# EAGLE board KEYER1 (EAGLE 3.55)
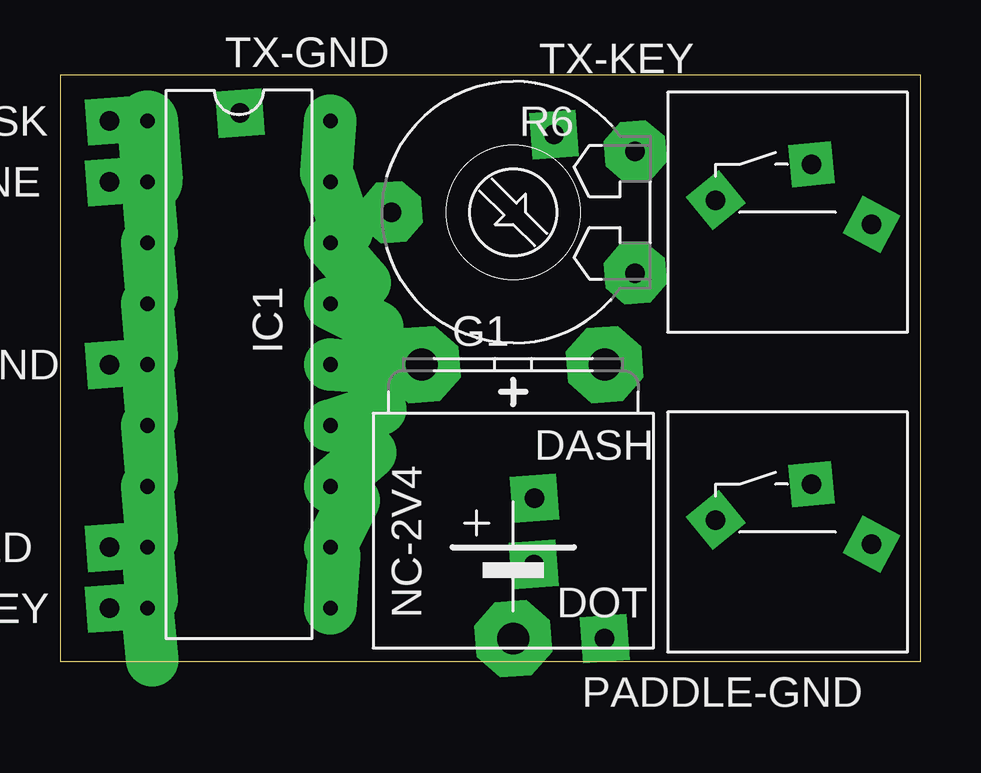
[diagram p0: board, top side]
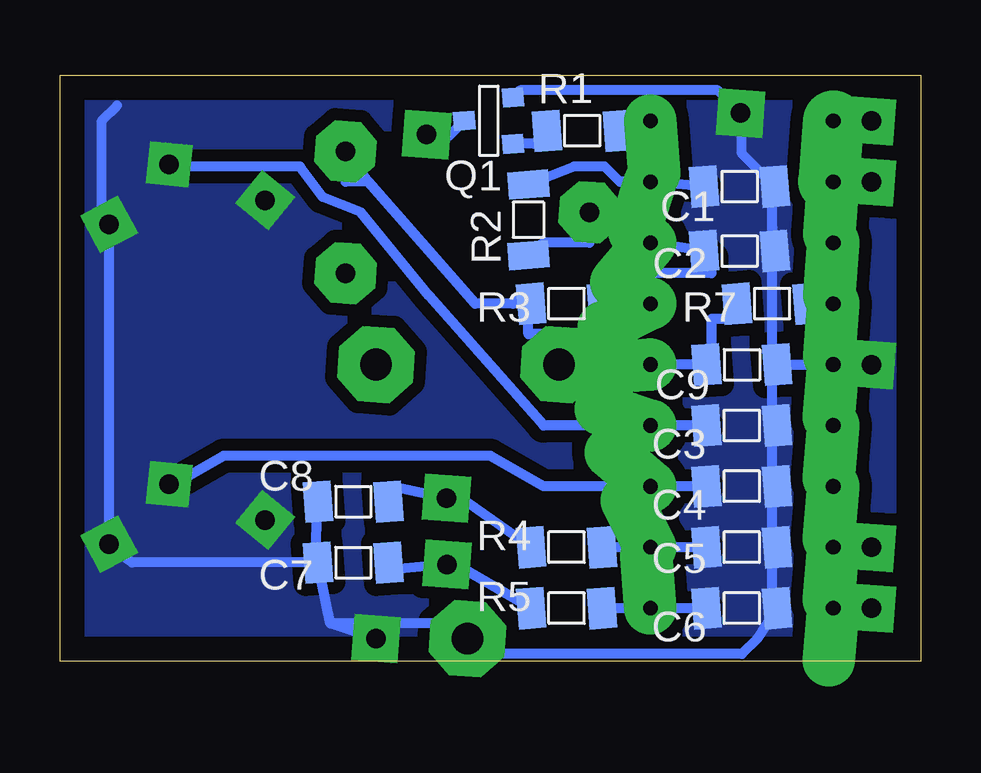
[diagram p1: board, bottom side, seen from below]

Size 35.87 x 24.44 mm. Coordinates in mm from the lower left corner, seen from the top.
Outline: 0,0 35.87,0 35.87,24.44 0,24.44 0,0
Copper layers used: Bottom

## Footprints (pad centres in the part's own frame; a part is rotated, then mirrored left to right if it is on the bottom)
06 = smd 1.143 x 1.702 rotated 4.4:  1.473,0 | smd 1.143 x 1.702 rotated 4.3:  -1.473,0
30R = drill 1.321 pad 3.15 octagon:  -7.62,-3.81;  -7.62,3.81;  3.81,0
L18 = drill 0.61 pad 2.54 offset:  -10.16,-3.81 | drill 0.61 pad 2.184 offset:  -7.62,-3.81;  5.08,-3.81;  7.62,-3.81;  -5.08,-3.81;  -2.54,-3.81;  2.54,-3.81;  0,-3.81;  10.16,-3.81;  10.16,3.81;  7.62,3.81;  5.08,3.81;  2.54,3.81;  0,3.81;  -2.54,3.81;  -5.08,3.81;  -7.62,3.81;  -10.16,3.81
T-23 = smd 0.787 x 0.889 rotated 4.4:  0.991,1.016 | smd 0.787 x 0.889 rotated 4.3:  -0.94,1.016 | smd 0.787 x 0.889 rotated 4.5:  0.025,-1.016
T_LI10 = drill 0.813 pad 2.54 octagon:  -2.54,-5.08;  0,5.08;  2.54,-5.08
Y_SQ10 = drill 0.813 pad 1.778 square:  -0.5,-3.5;  2,-1;  0.5,3
D-SQ2 = drill 0.813 pad 1.93 square:  0,0

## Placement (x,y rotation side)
C1  220n  [06]  7.55,19.8 0 bottom
C2  330pF  [06]  7.55,17.11 0 bottom
C3  1n  [06]  7.46,9.84 180 bottom
C4  1n  [06]  7.46,7.3 180 bottom
C5  1n  [06]  7.46,4.76 180 bottom
C6  1n  [06]  7.46,2.22 180 bottom
C7  1n  [06]  23.65,4.12 0 bottom
C8  1n  [06]  23.65,6.66 0 bottom
C9  100n  [06]  7.46,12.38 0 bottom
G1  NiCd2.4V  [30R]  18.88,4.76 270 top
IC1  16F84P  [L18]  7.46,12.38 270 top
Q1  BC817  [T-23]  18,22.57 270 bottom
R1  22k  [06]  14.1,22.12 180 bottom
R2  1k  [06]  16.34,18.41 270 bottom
R3  100k  [06]  14.76,14.92 180 bottom
R4  1k  [06]  14.76,4.76 180 bottom
R5  1k  [06]  14.76,2.22 180 bottom
R6  100k  [T_LI10]  18.88,18.73 90 top
R7  10k  [06]  6.18,14.92 180 bottom
S1  MSG1  [Y_SQ10]  30.31,5.39 90 top
S2  MSG2  [Y_SQ10]  30.31,18.73 90 top
X1  TX-KEY  [D-SQ2]  20.59,21.97 0 top
X2  DOT  [D-SQ2]  19.74,4.04 0 top
X3  DASH  [D-SQ2]  19.77,6.8 0 top
X4  PADDLE-GND  [D-SQ2]  22.7,0.95 0 top
X5  TX-GND  [D-SQ2]  7.5,22.86 0 top
X6  TONE  [D-SQ2]  2.06,20 0 top
X7  HAND-KEY  [D-SQ2]  2.06,2.22 0 top
X8  QSK  [D-SQ2]  2.06,22.54 0 top
X9  LED  [D-SQ2]  2.06,4.76 0 top
X10  GND  [D-SQ2]  2.06,12.38 0 top

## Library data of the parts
C1-C9 G1 IC1 Q1 R1-R7 S1 S2 X1-X10 = yhf_spec

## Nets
GND: C1. C2. C3. C4. C5. C6. C7. C8. C9. G1. IC1. Q1. S1. S2. X4. X5. X10.
N$1: IC1. R1.
N$2: C1. IC1. R2.
N$3: C2. IC1. R3.
N$4: R2. R6.
N$5: C5. IC1. R4.
N$6: C6. IC1. R5.
N$7: C3. IC1. S2.
N$8: C4. IC1. S1.
N$9: C7. R5. X2.
N$10: IC1. R7.
N$11: C8. R4. X3.
N$12: Q1. R1.
N$13: Q1. X1.
N$14: IC1. X6.
N$15: IC1. X7.
N$16: IC1. X8.
N$17: IC1. X9.
VBAT: C9. G1. IC1. R3. R6. R7.

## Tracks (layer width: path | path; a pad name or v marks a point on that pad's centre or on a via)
GND
  Bottom 0.406: 33.49,23.17 34.12,22.54 34.12,18.73 33.81,18.23 33.81,4.76 | 24.6,1.58 X4. | 24.6,1.58 20.15,1.58 G1. 18.25,0.31 7.46,0.31 6.82,0.95 C6. 6.18,2.85 6.18,4.12 C5. 6.18,5.39 6.18,6.66 C4. 6.18,7.93 6.18,9.2 C3. 6.18,10.47 6.18,11.74 5.98,12.38 | 5.98,12.38 3.64,12.38 | 5.98,12.38 6.18,13.01 6.18,16.82 6.08,17.11 6.18,18.09 6.18,19.36 6.08,19.8 7.46,21.18 7.46,22.86 X5. 8.45,23.81 16.69,23.81 16.99,23.51 | C7. 25.23,4.12 C8. | 24.6,1.58 C7. | C7. 32.85,4.12 33.81,4.76 | 33.81,4.76 33.81,4.89
  pour Bottom (isolate 0.508, no thermals): 0.15,24.44 0.15,-0.32 36.03,-0.32 36.03,24.44
N$1
  Bottom 0.406: R1. 12.54,22.21 12.54,22.22 11.58,22.22 IC1.
N$2
  Bottom 0.406: C1. 11.27,20 12.54,20 13.17,20.63 14.44,20.63 R2.
N$3
  Bottom 0.406: R3. 13.17,15.55 12.54,16.19 8.73,16.19 8.73,16.82 C2. 11.27,17.46
N$4
  Bottom 0.406: 16.34,16.94 15.71,17.46 13.81,17.46 13.81,18.73
N$5
  Bottom 0.406: 8.93,4.76 11.27,4.76 R4.
N$6
  Bottom 0.406: 8.93,2.22 11.27,2.22 R5.
N$7
  Bottom 0.406: 8.93,9.84 11.27,9.84 15.71,9.84 20.47,15.23 23.33,18.73 24.92,19.36 25.87,20.63 30.95,20.63 31.31,20.73
N$8
  Bottom 0.406: 8.93,7.3 11.27,7.3 15.71,7.3 17.93,8.57 29.04,8.57 31.27,7.3 31.31,7.39
N$9
  Bottom 0.406: 16.23,2.22 19.52,4.12 X2. 22.38,3.81 22.17,4.12
N$10
  Bottom 0.406: R7. 3.64,14.92
N$11
  Bottom 0.406: 16.23,4.76 19.84,7.3 X3. 22.06,7.3 22.17,6.66
N$12
  Bottom 0.406: 16.99,21.58 16.98,21.59 16.11,21.59 15.57,22.12
N$13
  Bottom 0.406: X1. 20.52,21.9 19.66,21.9 Q1.
N$14
  Bottom 0.406: X6. 3.64,20
N$15
  Bottom 0.406: X7. 3.64,2.22
N$16
  Bottom 0.406: X8. 3.64,22.54
N$17
  Bottom 0.406: X9. 3.64,4.76
VBAT
  Bottom 0.406: 7.66,14.92 8.09,14.28 8.73,14.28 8.73,13.01 C9. 11.27,12.38 15.08,12.38 15.71,13.65 16.34,13.65 16.34,14.92 | 23.01,20 18.57,14.92 16.98,14.92 | 16.98,14.92 16.34,15.55 | 23.01,20 23.96,20 | 23.01,20 R6. | 16.34,14.92 16.98,14.92 | 16.34,14.92 16.23,14.92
